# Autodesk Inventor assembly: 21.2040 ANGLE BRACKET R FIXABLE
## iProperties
Created: 2007-01
Part Number: 21.2040 ANGLE BRACKET R FIXABLE
Document SubType Name: Assembly
Designer: Andy Moles
Author: Andy Moles
